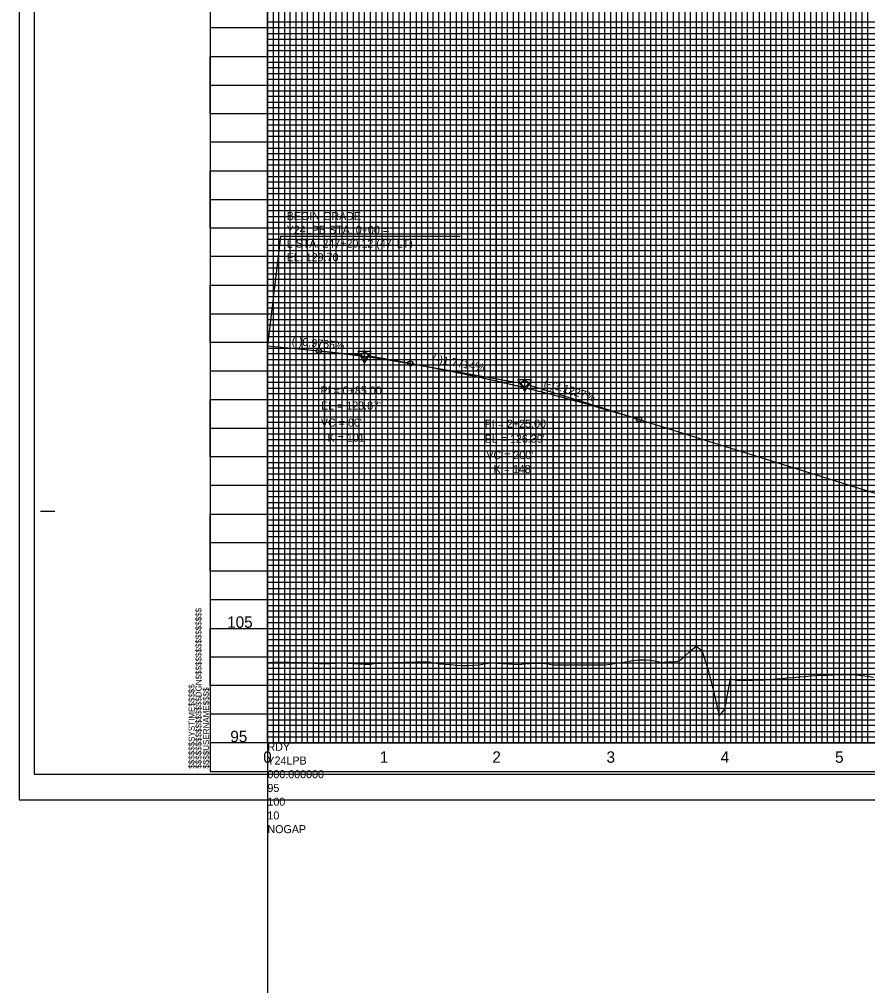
# Model space of a CAD drawing. Extents: x 2345490 to 2436403, y 465165 to 573888.
# Drawn here: x 2410678 to 2411420, y 532283 to 533128 of the extents above; entities that cross this region are included whole.
import ezdxf

# ---------------------------------------------------------------- set-up
doc = ezdxf.new("R2010")
doc.units = 0
for name, color, linetype in [('Old_Level_1', 7, 'Continuous'), ('Old_Level_18', 7, 'Continuous'), ('Old_Level_2', 7, 'Continuous'), ('Old_Level_40', 7, 'Continuous'), ('Old_Level_41', 7, 'Continuous'), ('Old_Level_42', 7, 'Continuous'), ('Old_Level_43', 7, 'Continuous'), ('Old_Level_50', 7, 'Continuous'), ('Old_Level_51', 7, 'Continuous'), ('Old_Level_52', 7, 'Continuous'), ('Old_Level_62', 7, 'Continuous'), ('Old_Level_63', 7, 'Continuous')]:
    doc.layers.add(name, color=color, linetype=linetype)

msp = doc.modelspace()

# ---------------------------------------------------------------- linework, layer by layer
at = {"layer": 'Old_Level_1'}
for points in [[(2410895.325, 532565.89775), (2410900.325, 532566.03475), (2410905.325, 532566.00325), (2410910.325, 532565.97175), (2410915.325, 532565.9395), (2410920.325, 532565.90675), (2410925.325, 532565.87325), (2410930.325, 532565.69825), (2410935.325, 532565.3215), (2410940.325, 532564.94525), (2410945.325, 532564.675), (2410950.325, 532564.95275), (2410955.325, 532565.23075), (2410960.325, 532565.39975), (2410965.325, 532565.1705), (2410970.325, 532564.93825), (2410975.325, 532564.70275), (2410980.325, 532564.464), (2410985.325, 532564.22175), (2410990.325, 532565.15675), (2410995.325, 532565.33075), (2411000.325, 532565.50175), (2411005.325, 532565.67025), (2411010.325, 532565.83575), (2411015.325, 532565.99825), (2411020.325, 532566.15775), (2411025.325, 532566.3225), (2411030.325, 532566.4945), (2411035.325, 532566.6625), (2411040.325, 532565.90475), (2411045.325, 532564.66825), (2411050.325, 532564.28125), (2411055.325, 532563.901), (2411060.325, 532563.5275), (2411065.325, 532563.161), (2411070.325, 532563.232), (2411075.325, 532563.5195), (2411080.325, 532563.81275), (2411085.325, 532564.65775), (2411090.325, 532565.48175), (2411095.325, 532565.21425), (2411100.325, 532564.94225), (2411105.325, 532564.666), (2411110.325, 532564.38525), (2411115.325, 532564.14825), (2411120.325, 532564.566), (2411125.325, 532564.8695), (2411130.325, 532565.154), (2411135.325, 532565.08825), (2411140.325, 532564.4825), (2411145.325, 532563.73925), (2411150.325, 532563.6915), (2411155.325, 532563.74675), (2411160.325, 532563.78525), (2411165.325, 532563.80725), (2411170.325, 532563.8375), (2411175.325, 532563.855), (2411180.325, 532563.855), (2411185.325, 532563.8365), (2411190.325, 532563.8), (2411195.325, 532564.3195), (2411200.325, 532565.10075), (2411205.325, 532565.89175), (2411210.325, 532566.67875), (2411215.325, 532567.4615), (2411220.325, 532568.01225), (2411225.325, 532568.148), (2411230.325, 532567.75475), (2411235.325, 532567.06875), (2411240.325, 532565.90175), (2411245.325, 532566.64175), (2411250.325, 532566.49575), (2411255.325, 532567.374), (2411260.325, 532571.329), (2411265.325, 532575.84225), (2411270.325, 532580.1485), (2411275.325, 532576.3265), (2411280.325, 532561.1185), (2411285.325, 532541.8785), (2411290.325, 532519.257), (2411295.325, 532524.89475), (2411300.325, 532551.4985), (2411305.325, 532550.331), (2411310.325, 532550.31575), (2411315.325, 532550.38225), (2411320.325, 532550.45675), (2411325.325, 532550.539), (2411330.325, 532550.601), (2411335.325, 532551.0005), (2411340.325, 532551.42875), (2411345.325, 532551.8595), (2411350.325, 532552.29225), (2411355.325, 532552.727), (2411360.325, 532553.16325), (2411365.325, 532553.60125), (2411370.325, 532554.03975), (2411375.325, 532554.34225), (2411380.325, 532554.58525), (2411385.325, 532554.83225), (2411390.325, 532555.08325), (2411395.325, 532555.2005)], [(2411395.325, 532555.2005), (2411400.325, 532555.219), (2411405.325, 532555.24175), (2411410.325, 532555.06925), (2411415.325, 532554.5325), (2411420.325, 532553.721), (2411425.325, 532552.97475)]]:
    msp.add_lwpolyline(points, dxfattribs=at)
at = {"layer": 'Old_Level_18'}
msp.add_line((2410845.325, 532470.5875), (2410845.325, 532470.5875), dxfattribs=at)
msp.add_line((2410845.325, 532470.5875), (2410845.325, 532470.5875), dxfattribs=at)
msp.add_lwpolyline([(2412345.325, 533520.5875), (2410845.325, 533520.5875), (2410845.325, 532470.5875), (2412345.325, 532470.5875)], close=True, dxfattribs=at)
at = {"layer": 'Old_Level_2'}
for p, q in [((2410906.6255, 532938.201), (2410895.325, 532842.5875)), ((2411063.7915, 532938.201), (2410906.6255, 532938.201)), ((2410895.325, 532842.5875), (2410940.325, 532838.1935)), ((2410940.325, 532838.1935), (2410977.58825, 532834.555)), ((2411020.325, 532827.202), (2410983.033, 532833.808)), ((2411020.325, 532827.202), (2411117.61725, 532809.9675)), ((2411220.325, 532778.261), (2411122.95, 532808.66825)), ((2411220.325, 532778.261), (2411720.325, 532622.1275))]:
    msp.add_line(p, q, dxfattribs=at)
for points in [[(2410986.19225, 532837.67), (2410974.44975, 532837.6555), (2410980.33325, 532827.53725)], [(2411126.19225, 532812.87025), (2411114.44975, 532812.85575), (2411120.33325, 532802.7375)]]:
    msp.add_lwpolyline(points, close=True, dxfattribs=at)
for centre, radius in [((2410940.325, 532838.1935), 2.25), ((2410980.325, 532834.2875), 2.75), ((2411020.325, 532827.202), 2.25), ((2411120.325, 532809.48775), 2.75), ((2411220.325, 532778.261), 2.25)]:
    msp.add_circle(centre, radius, dxfattribs=at)
for points in [[(2410940.325, 532838.1935), (2410941.925, 532838.036), (2410943.525, 532837.876), (2410945.125, 532837.71325), (2410946.725, 532837.54825), (2410948.325, 532837.3805), (2410949.925, 532837.21025), (2410951.525, 532837.0375), (2410953.125, 532836.86225), (2410954.725, 532836.68425), (2410956.325, 532836.504), (2410957.925, 532836.321), (2410959.525, 532836.1355), (2410961.125, 532835.9475), (2410962.725, 532835.757), (2410964.325, 532835.56375), (2410965.925, 532835.36825), (2410967.525, 532835.17), (2410969.125, 532834.96925), (2410970.725, 532834.76575), (2410972.325, 532834.56), (2410973.925, 532834.35175), (2410975.525, 532834.14075), (2410977.125, 532833.92725), (2410978.725, 532833.71125), (2410980.325, 532833.49275), (2410981.925, 532833.2715), (2410983.525, 532833.048), (2410985.125, 532832.82175), (2410986.725, 532832.593), (2410988.325, 532832.36175), (2410989.925, 532832.128), (2410991.525, 532831.8915), (2410993.125, 532831.6525), (2410994.725, 532831.41125), (2410996.325, 532831.16725), (2410997.925, 532830.9205), (2410999.525, 532830.6715), (2411001.125, 532830.42), (2411002.725, 532830.16575), (2411004.325, 532829.909), (2411005.925, 532829.64975), (2411007.525, 532829.388), (2411009.125, 532829.1235), (2411010.725, 532828.85675), (2411012.325, 532828.58725), (2411013.925, 532828.31525), (2411015.525, 532828.04075), (2411017.125, 532827.76375), (2411018.725, 532827.484), (2411020.325, 532827.202)], [(2411020.325, 532827.202), (2411024.325, 532826.488), (2411028.325, 532825.76325), (2411032.325, 532825.0275), (2411036.325, 532824.28125), (2411040.325, 532823.524), (2411044.325, 532822.756), (2411048.325, 532821.977), (2411052.325, 532821.1875), (2411056.325, 532820.387), (2411060.325, 532819.57575), (2411064.325, 532818.75375), (2411068.325, 532817.92075), (2411072.325, 532817.077), (2411076.325, 532816.2225), (2411080.325, 532815.35725), (2411084.325, 532814.481), (2411088.325, 532813.59425), (2411092.325, 532812.6965), (2411096.325, 532811.78775), (2411100.325, 532810.8685), (2411104.325, 532809.93825), (2411108.325, 532808.99725), (2411112.325, 532808.0455), (2411116.325, 532807.083), (2411120.325, 532806.1095), (2411124.325, 532805.12525), (2411128.325, 532804.13025), (2411132.325, 532803.1245), (2411136.325, 532802.10775), (2411140.325, 532801.08025), (2411144.325, 532800.042), (2411148.325, 532798.993), (2411152.325, 532797.933), (2411156.325, 532796.86225), (2411160.325, 532795.78075), (2411164.325, 532794.6885), (2411168.325, 532793.5855), (2411172.325, 532792.4715), (2411176.325, 532791.34675), (2411180.325, 532790.21125), (2411184.325, 532789.06475), (2411188.325, 532787.9075), (2411192.325, 532786.7395), (2411196.325, 532785.56075), (2411200.325, 532784.37125), (2411204.325, 532783.17075), (2411208.325, 532781.9595), (2411212.325, 532780.7375), (2411216.325, 532779.5045), (2411220.325, 532778.261)]]:
    msp.add_spline(points, degree=3, dxfattribs=at)
at = {"layer": 'Old_Level_40'}
msp.add_line((2410845.325, 532470.5875), (2410845.325, 532470.5875), dxfattribs=at)
msp.add_line((2410845.325, 532470.5875), (2410845.325, 532470.5875), dxfattribs=at)
msp.add_line((2410845.325, 532470.5875), (2410845.325, 532470.5875), dxfattribs=at)
msp.add_line((2410845.325, 532470.5875), (2410845.325, 532470.5875), dxfattribs=at)
at = {"layer": 'Old_Level_41'}
for p, q in [((2410696.825, 532698.0875), (2410709.325, 532698.0875)), ((2412345.325, 532495.5875), (2410845.325, 532495.5875))]:
    msp.add_line(p, q, dxfattribs=at)
for points in [[(2410845.325, 533520.5875), (2410895.325, 533520.5875), (2410895.325, 532495.5875), (2410945.325, 532495.5875), (2410945.325, 533520.5875), (2410995.325, 533520.5875), (2410995.325, 532495.5875), (2411045.325, 532495.5875), (2411045.325, 533520.5875), (2411095.325, 533520.5875), (2411095.325, 532495.5875), (2411145.325, 532495.5875), (2411145.325, 533520.5875), (2411195.325, 533520.5875), (2411195.325, 532495.5875), (2411245.325, 532495.5875), (2411245.325, 533520.5875), (2411295.325, 533520.5875), (2411295.325, 532495.5875), (2411345.325, 532495.5875), (2411345.325, 533520.5875), (2411395.325, 533520.5875), (2411395.325, 532495.5875), (2411445.325, 532495.5875)], [(2410920.325, 532495.5875), (2410920.325, 533520.5875), (2410970.325, 533520.5875), (2410970.325, 532495.5875), (2411020.325, 532495.5875), (2411020.325, 533520.5875), (2411070.325, 533520.5875), (2411070.325, 532495.5875), (2411120.325, 532495.5875), (2411120.325, 533520.5875), (2411170.325, 533520.5875), (2411170.325, 532495.5875), (2411220.325, 532495.5875), (2411220.325, 533520.5875), (2411270.325, 533520.5875), (2411270.325, 532495.5875), (2411320.325, 532495.5875), (2411320.325, 533520.5875), (2411370.325, 533520.5875), (2411370.325, 532495.5875), (2411420.325, 532495.5875), (2411420.325, 533520.5875), (2411470.325, 533520.5875)], [(2412345.325, 533120.5875), (2410845.325, 533120.5875), (2410845.325, 533070.5875), (2412345.325, 533070.5875)], [(2412345.325, 533020.5875), (2410845.325, 533020.5875), (2410845.325, 532970.5875), (2412345.325, 532970.5875)], [(2412345.325, 532920.5875), (2410845.325, 532920.5875), (2410845.325, 532870.5875), (2412345.325, 532870.5875)], [(2412345.325, 532845.5875), (2410845.325, 532845.5875), (2410845.325, 532895.5875), (2412345.325, 532895.5875)], [(2412345.325, 532820.5875), (2410845.325, 532820.5875), (2410845.325, 532770.5875), (2412345.325, 532770.5875)], [(2412345.325, 532745.5875), (2410845.325, 532745.5875), (2410845.325, 532795.5875), (2412345.325, 532795.5875)], [(2412345.325, 532720.5875), (2410845.325, 532720.5875), (2410845.325, 532670.5875), (2412345.325, 532670.5875)], [(2412345.325, 532620.5875), (2410845.325, 532620.5875), (2410845.325, 532570.5875), (2412345.325, 532570.5875)], [(2412345.325, 532545.5875), (2410845.325, 532545.5875), (2410845.325, 532595.5875), (2412345.325, 532595.5875)], [(2412345.325, 532520.5875), (2410845.325, 532520.5875)], [(2410882.825, 532470.5875), (2410882.825, 532470.5875)]]:
    msp.add_lwpolyline(points, dxfattribs=at)
at = {"layer": 'Old_Level_42'}
for points in [[(2412345.325, 533045.5875), (2410845.325, 533045.5875), (2410845.325, 533095.5875), (2412345.325, 533095.5875)], [(2412345.325, 532945.5875), (2410845.325, 532945.5875), (2410845.325, 532995.5875), (2412345.325, 532995.5875)], [(2412345.325, 532645.5875), (2410845.325, 532645.5875), (2410845.325, 532695.5875), (2412345.325, 532695.5875)]]:
    msp.add_lwpolyline(points, dxfattribs=at)
at = {"layer": 'Old_Level_43'}
for points in [[(2410900.325, 533520.5875), (2410900.325, 532495.5875), (2410905.325, 532495.5875), (2410905.325, 533520.5875)], [(2410910.325, 533520.5875), (2410910.325, 532495.5875), (2410915.325, 532495.5875), (2410915.325, 533520.5875)], [(2410925.325, 533520.5875), (2410925.325, 532495.5875), (2410930.325, 532495.5875), (2410930.325, 533520.5875)], [(2410935.325, 533520.5875), (2410935.325, 532495.5875), (2410940.325, 532495.5875), (2410940.325, 533520.5875)], [(2410950.325, 533520.5875), (2410950.325, 532495.5875), (2410955.325, 532495.5875), (2410955.325, 533520.5875)], [(2410960.325, 533520.5875), (2410960.325, 532495.5875), (2410965.325, 532495.5875), (2410965.325, 533520.5875)], [(2410975.325, 533520.5875), (2410975.325, 532495.5875), (2410980.325, 532495.5875), (2410980.325, 533520.5875)], [(2410985.325, 533520.5875), (2410985.325, 532495.5875), (2410990.325, 532495.5875), (2410990.325, 533520.5875)], [(2411000.325, 533520.5875), (2411000.325, 532495.5875), (2411005.325, 532495.5875), (2411005.325, 533520.5875)], [(2411010.325, 533520.5875), (2411010.325, 532495.5875), (2411015.325, 532495.5875), (2411015.325, 533520.5875)], [(2411025.325, 533520.5875), (2411025.325, 532495.5875), (2411030.325, 532495.5875), (2411030.325, 533520.5875)], [(2411035.325, 533520.5875), (2411035.325, 532495.5875), (2411040.325, 532495.5875), (2411040.325, 533520.5875)], [(2411050.325, 533520.5875), (2411050.325, 532495.5875), (2411055.325, 532495.5875), (2411055.325, 533520.5875)], [(2411060.325, 532495.5875), (2411065.325, 532495.5875), (2411065.325, 533520.5875)], [(2411060.325, 533520.5875), (2411060.325, 532495.5875)], [(2411075.325, 533520.5875), (2411075.325, 532495.5875), (2411080.325, 532495.5875), (2411080.325, 533520.5875)], [(2411085.325, 533520.5875), (2411085.325, 532495.5875), (2411090.325, 532495.5875), (2411090.325, 533520.5875)], [(2411100.325, 533520.5875), (2411100.325, 532495.5875), (2411105.325, 532495.5875), (2411105.325, 533520.5875)], [(2411110.325, 533520.5875), (2411110.325, 532495.5875), (2411115.325, 532495.5875), (2411115.325, 533520.5875)], [(2411125.325, 533520.5875), (2411125.325, 532495.5875), (2411130.325, 532495.5875), (2411130.325, 533520.5875)], [(2411135.325, 533520.5875), (2411135.325, 532495.5875), (2411140.325, 532495.5875), (2411140.325, 533520.5875)], [(2411150.325, 533520.5875), (2411150.325, 532495.5875), (2411155.325, 532495.5875), (2411155.325, 533520.5875)], [(2411160.325, 533520.5875), (2411160.325, 532495.5875), (2411165.325, 532495.5875), (2411165.325, 533520.5875)], [(2411175.325, 533520.5875), (2411175.325, 532495.5875), (2411180.325, 532495.5875), (2411180.325, 533520.5875)], [(2411185.325, 533520.5875), (2411185.325, 532495.5875), (2411190.325, 532495.5875), (2411190.325, 533520.5875)], [(2411200.325, 533520.5875), (2411200.325, 532495.5875), (2411205.325, 532495.5875), (2411205.325, 533520.5875)], [(2411210.325, 533520.5875), (2411210.325, 532495.5875), (2411215.325, 532495.5875), (2411215.325, 533520.5875)], [(2411225.325, 533520.5875), (2411225.325, 532495.5875), (2411240.325, 532495.5875), (2411240.325, 533520.5875)], [(2411230.325, 533520.5875), (2411230.325, 532495.5875), (2411235.325, 532495.5875), (2411235.325, 533520.5875)], [(2411230.325, 533519.9875), (2411230.325, 532495.5875), (2411235.325, 532495.5875), (2411235.325, 533519.9875)], [(2411250.325, 533520.5875), (2411250.325, 532495.5875), (2411255.325, 532495.5875), (2411255.325, 533520.5875)], [(2411260.325, 533520.5875), (2411260.325, 532495.5875), (2411265.325, 532495.5875), (2411265.325, 533520.5875)], [(2411275.325, 533520.5875), (2411275.325, 532495.5875), (2411280.325, 532495.5875), (2411280.325, 533520.5875)], [(2411285.325, 533520.5875), (2411285.325, 532495.5875), (2411290.325, 532495.5875), (2411290.325, 533520.5875)], [(2411300.325, 533520.5875), (2411300.325, 532495.5875), (2411305.325, 532495.5875), (2411305.325, 533520.5875)], [(2411310.325, 533520.5875), (2411310.325, 532495.5875), (2411315.325, 532495.5875), (2411315.325, 533520.5875)], [(2411325.325, 533520.5875), (2411325.325, 532495.5875), (2411330.325, 532495.5875), (2411330.325, 533520.5875)], [(2411335.325, 533520.5875), (2411335.325, 532495.5875), (2411340.325, 532495.5875), (2411340.325, 533520.5875)], [(2411350.325, 533520.5875), (2411350.325, 532495.5875), (2411355.325, 532495.5875), (2411355.325, 533520.5875)], [(2411360.325, 533520.5875), (2411360.325, 532495.5875), (2411365.325, 532495.5875), (2411365.325, 533520.5875)], [(2411375.325, 533520.5875), (2411375.325, 532495.5875)], [(2411380.325, 533520.5875), (2411380.325, 532495.5875), (2411385.325, 532495.5875), (2411385.325, 533520.5875), (2411390.325, 533520.5875), (2411390.325, 532495.5875), (2411400.325, 532495.5875), (2411400.325, 533520.5875), (2411405.325, 533520.5875), (2411405.325, 532495.5875), (2411410.325, 532495.5875), (2411410.325, 533520.5875), (2411415.325, 533520.5875), (2411415.325, 532495.5875)], [(2412295.325, 533125.5875), (2410895.325, 533125.5875), (2410895.325, 533115.5875), (2412295.325, 533115.5875)], [(2412295.325, 533110.5875), (2410895.325, 533110.5875), (2410895.325, 533105.5875), (2412295.325, 533105.5875)], [(2412295.325, 533100.5875), (2410895.325, 533100.5875), (2410895.325, 533090.5875), (2412295.325, 533090.5875)], [(2412295.325, 533085.5875), (2410895.325, 533085.5875), (2410895.325, 533080.5875), (2412295.325, 533080.5875)], [(2412295.325, 533075.5875), (2410895.325, 533075.5875), (2410895.325, 533065.5875), (2412295.325, 533065.5875)], [(2412295.325, 533060.5875), (2410895.325, 533060.5875), (2410895.325, 533055.5875), (2412295.325, 533055.5875)], [(2412295.325, 533050.5875), (2410895.325, 533050.5875), (2410895.325, 533040.5875), (2412295.325, 533040.5875)], [(2412295.325, 533035.5875), (2410895.325, 533035.5875), (2410895.325, 533030.5875), (2412295.325, 533030.5875)], [(2412295.325, 533025.5875), (2410895.325, 533025.5875), (2410895.325, 533015.5875), (2412295.325, 533015.5875)], [(2412295.325, 533010.5875), (2410895.325, 533010.5875), (2410895.325, 533005.5875), (2412295.325, 533005.5875)], [(2412295.325, 533000.5875), (2410895.325, 533000.5875)], [(2410895.325, 532990.5875), (2412295.325, 532990.5875)], [(2412295.325, 532985.5875), (2410895.325, 532985.5875), (2410895.325, 532980.5875), (2412295.325, 532980.5875)], [(2412295.325, 532975.5875), (2410895.325, 532975.5875), (2410895.325, 532965.5875), (2412295.325, 532965.5875)], [(2412295.325, 532960.5875), (2410895.325, 532960.5875), (2410895.325, 532955.5875), (2412295.325, 532955.5875)], [(2412295.325, 532950.5875), (2410895.325, 532950.5875), (2410895.325, 532940.5875), (2412295.325, 532940.5875)], [(2412295.325, 532935.5875), (2410895.325, 532935.5875), (2410895.325, 532930.5875), (2412295.325, 532930.5875)], [(2412295.325, 532925.5875), (2410895.325, 532925.5875), (2410895.325, 532915.5875), (2412295.325, 532915.5875)], [(2412295.325, 532910.5875), (2410895.325, 532910.5875), (2410895.325, 532905.5875), (2412295.325, 532905.5875)], [(2412295.325, 532900.5875), (2410895.325, 532900.5875), (2410895.325, 532890.5875), (2412295.325, 532890.5875)], [(2412295.325, 532885.5875), (2410895.325, 532885.5875), (2410895.325, 532880.5875), (2412295.325, 532880.5875)], [(2412295.325, 532875.5875), (2410895.325, 532875.5875), (2410895.325, 532865.5875), (2412295.325, 532865.5875)], [(2412295.325, 532860.5875), (2410895.325, 532860.5875), (2410895.325, 532855.5875), (2412295.325, 532855.5875)], [(2412295.325, 532850.5875), (2410895.325, 532850.5875), (2410895.325, 532840.5875), (2412295.325, 532840.5875)], [(2412295.325, 532835.5875), (2410895.325, 532835.5875), (2410895.325, 532830.5875), (2412295.325, 532830.5875)], [(2412295.325, 532825.5875), (2410895.325, 532825.5875), (2410895.325, 532815.5875), (2412295.325, 532815.5875)], [(2412295.325, 532810.5875), (2410895.325, 532810.5875), (2410895.325, 532805.5875), (2412295.325, 532805.5875)], [(2412295.325, 532800.5875), (2410895.325, 532800.5875), (2410895.325, 532790.5875), (2412295.325, 532790.5875)], [(2412295.325, 532785.5875), (2410895.325, 532785.5875), (2410895.325, 532780.5875), (2412295.325, 532780.5875)], [(2412295.325, 532775.5875), (2410895.325, 532775.5875), (2410895.325, 532765.5875), (2412295.325, 532765.5875)], [(2412295.325, 532760.5875), (2410895.325, 532760.5875), (2410895.325, 532755.5875), (2412295.325, 532755.5875)], [(2412295.325, 532750.5875), (2410895.325, 532750.5875), (2410895.325, 532740.5875), (2412295.325, 532740.5875)], [(2412295.325, 532735.5875), (2410895.325, 532735.5875), (2410895.325, 532730.5875), (2412295.325, 532730.5875)], [(2412295.325, 532725.5875), (2410895.325, 532725.5875), (2410895.325, 532715.5875), (2412295.325, 532715.5875)], [(2412295.325, 532710.5875), (2410895.325, 532710.5875), (2410895.325, 532705.5875), (2412295.325, 532705.5875)], [(2412295.325, 532700.5875), (2410895.325, 532700.5875)], [(2410895.325, 532690.5875), (2412295.325, 532690.5875)], [(2412295.325, 532685.5875), (2410895.325, 532685.5875), (2410895.325, 532680.5875), (2412295.325, 532680.5875)], [(2412295.325, 532675.5875), (2410895.325, 532675.5875)], [(2410895.325, 532665.5875), (2412295.325, 532665.5875)], [(2412295.325, 532660.5875), (2410895.325, 532660.5875), (2410895.325, 532655.5875), (2412295.325, 532655.5875)], [(2412295.325, 532650.5875), (2410895.325, 532650.5875), (2410895.325, 532640.5875), (2412295.325, 532640.5875)], [(2412295.325, 532635.5875), (2410895.325, 532635.5875), (2410895.325, 532630.5875), (2412295.325, 532630.5875)], [(2412295.325, 532625.5875), (2410895.325, 532625.5875), (2410895.325, 532615.5875), (2412295.325, 532615.5875)], [(2412295.325, 532610.5875), (2410895.325, 532610.5875), (2410895.325, 532605.5875), (2412295.325, 532605.5875)], [(2412295.325, 532600.5875), (2410895.325, 532600.5875), (2410895.325, 532590.5875), (2412295.325, 532590.5875)], [(2412295.325, 532585.5875), (2410895.325, 532585.5875), (2410895.325, 532580.5875), (2412295.325, 532580.5875)], [(2412295.325, 532575.5875), (2410895.325, 532575.5875), (2410895.325, 532565.5875), (2412295.325, 532565.5875)], [(2412295.325, 532560.5875), (2410895.325, 532560.5875), (2410895.325, 532555.5875), (2412295.325, 532555.5875)], [(2412295.325, 532550.5875), (2410895.325, 532550.5875), (2410895.325, 532540.5875), (2412295.325, 532540.5875)], [(2412295.325, 532535.5875), (2410895.325, 532535.5875), (2410895.325, 532530.5875), (2412295.325, 532530.5875)], [(2412295.325, 532525.5875), (2410895.325, 532525.5875), (2410895.325, 532515.5875), (2412295.325, 532515.5875)], [(2412295.325, 532510.5875), (2410895.325, 532510.5875), (2410895.325, 532505.5875), (2412295.325, 532505.5875)], [(2412295.325, 532500.5875), (2410895.325, 532500.5875)]]:
    msp.add_lwpolyline(points, dxfattribs=at)
at = {"layer": 'Old_Level_50'}
msp.add_line((2410678.325, 532445.5875), (2410678.325, 532445.5875), dxfattribs=at)
msp.add_lwpolyline([(2412357.825, 533523.1375), (2410691.325, 533523.1375), (2410691.325, 532468.0375), (2412357.825, 532468.0375)], close=True, dxfattribs=at)
at = {"layer": 'Old_Level_51'}
msp.add_lwpolyline([(2412362.325, 533545.5875), (2410678.325, 533545.5875), (2410678.325, 532445.5875), (2412362.325, 532445.5875)], close=True, dxfattribs=at)
at = {"layer": 'Old_Level_52'}
msp.add_line((2410691.325, 532468.0375), (2410691.325, 532468.0375), dxfattribs=at)
at = {"layer": 'Old_Level_63'}
for p, q in [((2410895.325, 532495.5875), (2410895.325, 534995.5875)), ((2411045.325, 532822.8475), (2411045.325, 533059.822)), ((2411095.325, 532813.8475), (2411095.325, 533059.822)), ((2411145.325, 532800.0675), (2411145.325, 533059.822)), ((2410895.325, 532842.5875), (2410895.325, 532634.61525)), ((2410945.325, 532837.7175), (2410945.325, 532634.61525)), ((2410995.325, 532831.2875), (2410995.325, 532634.61525)), ((2411045.325, 532821.5175), (2411045.325, 532634.61525)), ((2411095.325, 532805.2875), (2411095.325, 532634.61525)), ((2411145.325, 532783.3575), (2411145.325, 532634.61525)), ((2410895.325, 532495.5875), (2412059.1905, 532495.5875)), ((2410895.325, 532495.5875), (2410895.325, 529995.5875))]:
    msp.add_line(p, q, dxfattribs=at)

# ---------------------------------------------------------------- texts
at = {"layer": 'Old_Level_2'}
for s, height, p in [('BEGIN GRADE', 7.0000005, (2410912.216, 532952.588)), ('Y24LPB STA. 0+00 =', 7.0000005, (2410912.216, 532940.588)), ("L STA. 247+20.12 (47' LT)", 7.0000005, (2410912.216, 532928.588)), ('EL. 129.70', 7.000001, (2410912.216, 532916.588)), ('PI = 0+85.00', 7.0000005, (2410941.6585, 532800.09425)), ("EL = 128.87'", 7.0000005, (2410942.18225, 532786.906)), ("VC = 80'", 7.000001, (2410942.088, 532772.0585)), ('PI = 2+25.00', 7.0000005, (2411085.325, 532771.10275)), ('K = 101', 7.000001, (2410947.84975, 532758.8115)), ("EL = 126.39'", 7.0000005, (2411085.325, 532757.9145)), ("VC = 200'", 7.000001, (2411086.80225, 532743.59075)), ('K = 148', 7.000001, (2411093.08775, 532731.392))]:
    msp.add_text(s, height=height, dxfattribs=at).set_placement(p)
for s, rotation, p in [('(-)0.9765%', 354.42291667, (2410916.344, 532843.54975)), ('(-)1.7714%', 349.95466944, (2411039.002, 532828.23975)), ('(-)3.1227%', 342.65815556, (2411136.62375, 532807.54125))]:
    msp.add_text(s, height=7.000001, rotation=rotation, dxfattribs=at).set_placement(p)
at = {"layer": 'Old_Level_41'}
for s, p in [('$$$$$$$$$$$$$$$$DGN$$$$$$$$$$$$$$$$', (2410837.675, 532472.95)), ('$$$$$$SYSTIME$$$$$', (2410831.625, 532472.95)), ('$$$$USERNAME$$$$', (2410844.25, 532472.9625))]:
    msp.add_text(s, height=5.25, rotation=90, dxfattribs=at).set_placement(p)
at = {"layer": 'Old_Level_62'}
for s, height, p in [('105', 10.000001, (2410860.1115, 532596.0875)), ('95', 10.000001, (2410862.869, 532496.0875)), ('0', 10, (2410891.666, 532478.0875)), ('1', 10, (2410993.5055, 532478.0875)), ('2', 10, (2411092.054, 532478.0875)), ('3', 10, (2411191.88875, 532478.0875)), ('4', 10, (2411291.731, 532478.0875)), ('5', 10, (2411391.8235, 532478.0875))]:
    msp.add_text(s, height=height, dxfattribs=at).set_placement(p)
at = {"layer": 'Old_Level_63'}
for s, p in [('RDY', (2410895.325, 532488.5875)), ('Y24LPB', (2410895.325, 532476.5875)), ('000.000000', (2410895.325, 532464.5875)), ('95', (2410895.325, 532452.5875)), ('100', (2410895.325, 532440.5875)), ('10', (2410895.325, 532428.5875)), ('NOGAP', (2410895.325, 532416.5875))]:
    msp.add_text(s, height=7.000001, dxfattribs=at).set_placement(p)

doc.saveas('drawing.dxf')
